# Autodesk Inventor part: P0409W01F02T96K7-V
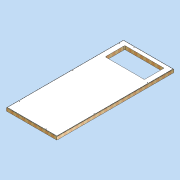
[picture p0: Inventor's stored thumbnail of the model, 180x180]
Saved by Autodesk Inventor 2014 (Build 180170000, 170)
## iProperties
Created: 2011-04
Part Number: P0409W01F02T96K7-V
Document SubType Name: Modeling
Designer: david.appleford
Density: 1 g/cm^3
Description: 1w x 2w  01 Panel - 6 Locks
Cost Center: £143.00
Mass: 213418 g
Surface Area: 61856.7 cm^2
Volume: 213418 cm^3
Material: Generic
Appearance: Wood (Pine)
Justset: False
Title: 1w x 2w  01 Panel - 6 Locks
Author: david.appleford
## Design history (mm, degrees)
sketch "Sketch1"
  geometry: L1 (0, 0)-(1220, 0); L2 (1220, 0)-(1220, 2745); L3 (1220, 2745)-(0, 2745); L4 (0, 2745)-(0, 0); L5 (34, 2711)-(1186, 2711); L6 (1186, 2711)-(1186, 34); L7 (1186, 34)-(34, 34); L8 (34, 34)-(34, 2711)
  constraints: 16 end point, 4 parallel, 2 perpendicular, 1 horizontal, 3 other
  dimensions: "d0" = 1220 distance between parallel lines of L2 L4 (= w); "d1" = 2745 distance between parallel lines of L1 L3 (= 2.25 x w); "d2" = 34 distance between parallel lines of L5 L3 (= 0.5 x t); "d29" = 2677 distance between parallel lines of L7 L5 (derived); "d30" = 1152 distance between parallel lines of L6 L8 (derived)
extrude "Extrusion1" new body sketch "Sketch1" distance "d3" = 68 (= t); taper "d4" = 0 deg
sketch "Sketch2"
  geometry: L1 (1186, 2711)-(1186, 34) reference; L2 (34, 2711)-(1186, 2711) reference; L3 (34, 34)-(34, 2711) reference; L4 (1186, 34)-(34, 34) reference; L5 (1176, 2701)-(1176, 44); L6 (1176, 44)-(44, 44); L7 (44, 44)-(44, 2701); L8 (44, 2701)-(1176, 2701); 1 further point
  constraints: 8 end point, 3 other
  dimensions: "d5" = 10 distance between parallel lines of L8 L2
extrude "Extrusion2" join sketch "Sketch2" distance "d6" = 6 (= sw); taper "d7" = 0 deg
sketch "Sketch3"
  geometry: L1 (-44, 2701)-(-1176, 2701) reference; L2 (-1176, 2701)-(-1176, 44) reference; L3 (-44, 44)-(-44, 2701) reference; L4 (-1176, 44)-(-44, 44) reference; 1 further point
extrude "Extrusion3" join sketch "Sketch3" distance "d8" = 6 (= sw); taper "d9" = 0 deg
sketch "Sketch4"
  geometry: L1 (34, 2711)-(1186, 2711) reference; L2 (1186, 2711)-(1186, 34) reference; L3 (1186, 34)-(34, 34) reference; L4 (34, 34)-(34, 2711) reference; 8 further points
  constraints: 3 vertical alignment
  dimensions: "d10" = 28 distance from line of point (305, 2683) L1 (= k); "d12" = 28 distance from line of L3 point (915, 62) (= k); "d13" = 28 distance from line of point (62, 305) L4 (= k); "d14" = 305 horizontal distance of point (305, 2683) point (0, 0) (= 0.25 x w); "d15" = 610 horizontal distance of point (915, 62) point (305, 2683) (= 0.5 x w); "d16" = 305 vertical distance of point (62, 305) point (0, 0) (= 0.25 x w); "d17" = 1220 distance of point (62, 305) point (62, 1525) (= w); "d19" = 610 vertical distance of point (1158, 915) point (62, 305) (= 0.5 x w); "d20" = 1220 distance of point (1158, 915) point (1158, 2135) (= w); "d31" = 1067.5 distance of point (62, 1525) point (62, 2592.5)
hole "Hole1" sketch "Sketch4" at (305, 2683), (62, 1525), (62, 305), (1158, 2135), (1158, 915), (915, 62), (62, 2592.5) diameter "d22" = 12 (= hd); stored, may be unused: countersink angle "d26" = 90 deg, drill point angle "d28" = 118 deg; dims "d23" = 6, "d24" = 4, "d25" = 2, "d27" = 8
sketch "Sketch5"
  geometry: L1 (180, 2615)-(1040, 2615); L2 (1060, 2595)-(1060, 2185); L3 (1040, 2165)-(180, 2165); L4 (160, 2185)-(160, 2595); L5 (34, 2711)-(1186, 2711) reference; L6 (34, 34)-(34, 2711) reference; L7 (1186, 2711)-(1186, 34) reference; A1 r 20 centre (180, 2595) between (180, 2615) and (160, 2595); A2 r 20 centre (1040, 2595) between (1060, 2595) and (1040, 2615); A3 r 20 centre (1040, 2185) between (1040, 2165) and (1060, 2185); A4 r 20 centre (180, 2185) between (160, 2185) and (180, 2165); 1 further point
  constraints: 8 end point, 8 point on circle, 8 tangent, 4 centre point, 3 equal radius
  dimensions: "d32" = 96 distance between parallel lines of L5 L1; "d33" = 450 distance between parallel lines of L3 L1; "d34" = 126 distance between parallel lines of L6 L4 (= -0.5 x d36 + 0.5 x d35); "d35" = 1152 distance between parallel lines of L7 L6 (derived); "d36" = 900 distance between parallel lines of L2 L4; "d37" = 20 radius of A1
extrude "Extrusion4" cut sketch "Sketch5" stored distance "d38" = 10; taper "d39" = 0 deg
body "Solid1"
node "Projected Loop1"
other parameters: "w" = 1220 [user parameter; used in 8 equation terms], "t" = 68 [user parameter; used in 2 equation terms], "e" = 16 [user parameter], "sw" = 6 [user parameter; used in 2 equation terms], "sc" = 9 [user parameter], "sf" = 12 [user parameter], "k" = 28 [user parameter; used in 3 equation terms], "hd" = 12 [user parameter; used in 1 equation term]
